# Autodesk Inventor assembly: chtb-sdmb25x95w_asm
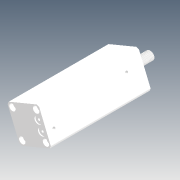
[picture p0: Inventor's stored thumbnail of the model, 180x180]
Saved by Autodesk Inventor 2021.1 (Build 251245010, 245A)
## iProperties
Company: Microsoft
Created: 2018-05
Part Number: chtb-sdmb25x95w_asm
Description: STEP AP214
Document SubType Name: Assembly
Designer: user
Title: chtb-sdmb25x95w_asm.STEP
Author: Windows
Revision Number: ÈÎºÎ
Sending System: SolidWorks 2015
Preprocessor: SwSTEP 2.0
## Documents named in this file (4)
- D:\Vault_2016\Projekty\Clamptek\Hydraulic\CHTB\CHTB-25\Inventor\chtb-sdmb25x95w\chtb-sdmb25x95w_asm.iam
- D:\Vault_2016\Projekty\Clamptek\Hydraulic\CHTB\CHTB-25\Inventor\chtb-sdmb25x95w\CHTB-25QG.ipt
- D:\Vault_2016\Projekty\Clamptek\Hydraulic\CHTB\CHTB-25\Inventor\chtb-sdmb25x95w\CHTB-SDMB25X95NBT.ipt
- D:\Vault_2016\Projekty\Clamptek\Hydraulic\CHTB\CHTB-25\Inventor\chtb-sdmb25x95w\CHTB-SDMB25X95WHSG.ipt
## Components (3 placed, 3 different names)
1. CHTB-25QG_1
2. CHTB-SDMB25X95NBT_2
3. CHTB-SDMB25X95WHSG_3
